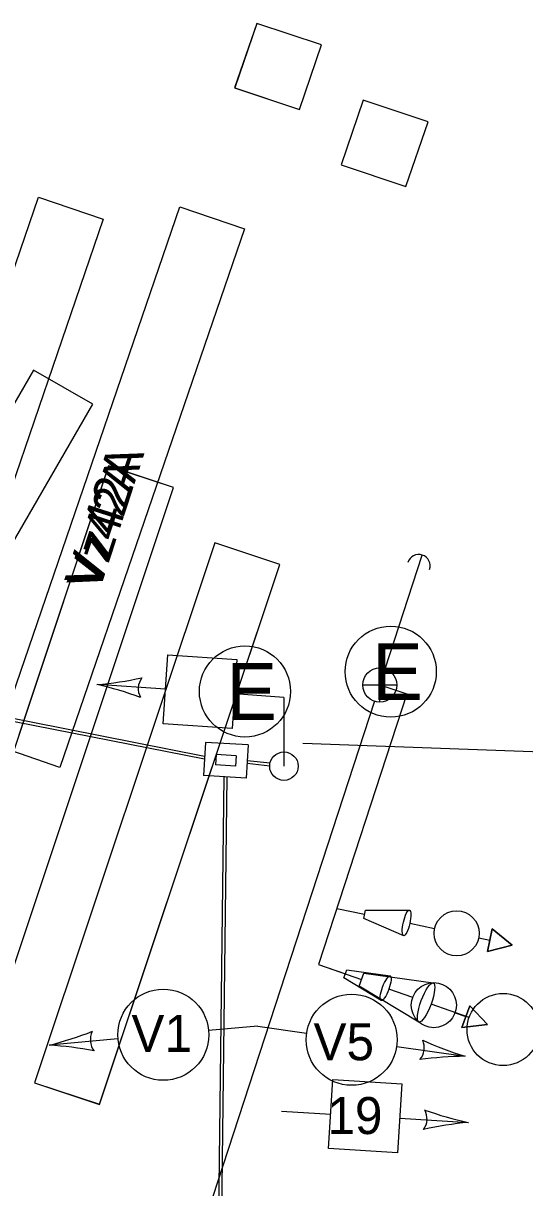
# Model space of a CAD drawing. Extents: x 647787 to 668496, y 640478 to 654412.
# Drawn here: x 661870.2 to 661914.2, y 647344.9 to 647447.2 of the extents above; entities that cross this region are included whole.
import ezdxf

# ---------------------------------------------------------------- set-up
doc = ezdxf.new("R2010")
doc.units = 0
for name, color, linetype in [('TEMP_DETECTION ZONE_STAGE 3', 7, 'Continuous'), ('TEMP_DETECTION_ZONE_STAGE 5', 7, 'Continuous'), ('TEMP_SIGNAL_HEAD_PED STAGES 1C', 7, 'Continuous'), ('TEMP_SIGNAL_HEAD_STAGE 1A', 7, 'Continuous'), ('TEMP_SIGNAL_HEAD_STAGE 2', 7, 'Continuous'), ('TEMP_SIGNAL_HEAD_STAGE 3 SHILO', 7, 'Continuous'), ('TEMP_SIGNAL_POLES_STAGE 1A', 7, 'Continuous'), ('TEMP_SIGNAL_POLES_STAGE 1B', 7, 'Continuous'), ('TEMP_SIGNAL_POLES_STAGE 2', 7, 'Continuous'), ('TEMP_SIGNAL_POLES_STAGE 3-1', 7, 'Continuous'), ('TEMP_SIGNAL_POLES_STAGE 5', 7, 'Continuous'), ('TEMP_SIGNAL_POLES_STAGES 3-4', 7, 'Continuous'), ('TEXT_TEMP_SIGNAL_POLES_STAGE 2', 7, 'Continuous'), ('TEXT_TEMP_SIGNAL_POLES_STAGE 3', 7, 'Continuous'), ('TEXT_TEMP_SIGNAL_POLES_STAGE 4', 7, 'Continuous'), ('TEXT_TEMP_SIGNAL_POLES_STAGE 5', 7, 'Continuous')]:
    doc.layers.add(name, color=color, linetype=linetype)

msp = doc.modelspace()

# ---------------------------------------------------------------- linework, layer by layer
at = {"layer": 'TEMP_DETECTION ZONE_STAGE 3'}
for points in [[(661890.66, 647447.21), (661888.71, 647441.54), (661894.41, 647439.64), (661896.35, 647445.31)], [(661890.66, 647447.21), (661888.71, 647441.54), (661894.41, 647439.64), (661896.35, 647445.31)], [(661890.66, 647447.21), (661888.71, 647441.54), (661894.41, 647439.64), (661896.35, 647445.31)], [(661890.66, 647447.21), (661888.72, 647441.54), (661894.41, 647439.64), (661896.35, 647445.31)], [(661900.01, 647440.47), (661898.06, 647434.79), (661903.75, 647432.89), (661905.7, 647438.57)], [(661900.01, 647440.47), (661898.06, 647434.79), (661903.75, 647432.89), (661905.7, 647438.57)], [(661900.01, 647440.47), (661898.06, 647434.79), (661903.75, 647432.89), (661905.7, 647438.57)], [(661900.01, 647440.47), (661898.06, 647434.79), (661903.75, 647432.89), (661905.7, 647438.57)], [(661846.03, 647373.46), (661851.22, 647370.46), (661876.25, 647413.75), (661871.05, 647416.75)], [(661846.03, 647373.46), (661851.22, 647370.46), (661876.25, 647413.75), (661871.05, 647416.75)], [(661846.03, 647373.46), (661851.22, 647370.46), (661876.25, 647413.75), (661871.05, 647416.75)], [(661846.03, 647373.47), (661851.22, 647370.46), (661876.25, 647413.75), (661871.06, 647416.75)], [(661861.82, 647360.91), (661867.51, 647359.01), (661883.34, 647406.44), (661877.65, 647408.34)], [(661861.82, 647360.91), (661867.51, 647359.01), (661883.34, 647406.43), (661877.64, 647408.33)], [(661861.82, 647360.91), (661867.51, 647359.01), (661883.34, 647406.43), (661877.64, 647408.33)], [(661861.82, 647360.91), (661867.51, 647359.01), (661883.34, 647406.43), (661877.64, 647408.33)], [(661871.15, 647354.16), (661876.84, 647352.26), (661892.67, 647399.69), (661886.98, 647401.59)], [(661871.15, 647354.16), (661876.84, 647352.26), (661892.67, 647399.69), (661886.98, 647401.59)], [(661871.15, 647354.16), (661876.84, 647352.26), (661892.67, 647399.69), (661886.98, 647401.59)], [(661871.15, 647354.17), (661876.85, 647352.27), (661892.67, 647399.69), (661886.98, 647401.59)]]:
    msp.add_lwpolyline(points, close=True, dxfattribs=at)
at = {"layer": 'TEMP_DETECTION_ZONE_STAGE 5'}
for points in [[(661860.97, 647382.71), (661855.29, 647384.65), (661871.5, 647431.95), (661877.18, 647430.01)], [(661873.37, 647381.86), (661867.69, 647383.8), (661883.89, 647431.1), (661889.57, 647429.16)]]:
    msp.add_lwpolyline(points, close=True, dxfattribs=at)
at = {"layer": 'TEMP_SIGNAL_HEAD_PED STAGES 1C'}
for points in [[(661897.68, 647369.47), (661900.13, 647368.96)], [(661897.68, 647369.47), (661900.13, 647368.96)], [(661900.05, 647368.59), (661900.21, 647369.32)], [(661900.05, 647368.59), (661900.21, 647369.32)], [(661900.21, 647369.32), (661904.06, 647369.32)], [(661900.21, 647369.32), (661904.06, 647369.32)], [(661903.57, 647367.08), (661900.05, 647368.59)], [(661903.57, 647367.08), (661900.05, 647368.59)], [(661906.27, 647367.69), (661904.09, 647368.14)], [(661906.27, 647367.69), (661904.09, 647368.14)], [(661910.91, 647365.69), (661911.34, 647367.67), (661913.09, 647366.25), (661910.91, 647365.69)], [(661910.91, 647365.69), (661911.34, 647367.67), (661913.09, 647366.25), (661910.91, 647365.69)], [(661910.15, 647366.89), (661911.12, 647366.68)], [(661910.15, 647366.89), (661911.12, 647366.68)], [(661896.08, 647364.56), (661898.44, 647363.73)], [(661896.08, 647364.56), (661898.44, 647363.73)], [(661898.31, 647363.37), (661898.56, 647364.07)], [(661898.31, 647363.37), (661898.56, 647364.07)], [(661898.56, 647364.07), (661902.38, 647363.55)], [(661898.56, 647364.07), (661902.38, 647363.55)], [(661901.59, 647361.39), (661898.31, 647363.37)], [(661901.59, 647361.39), (661898.31, 647363.37)], [(661904.35, 647361.64), (661902.25, 647362.38)], [(661904.35, 647361.64), (661902.25, 647362.38)], [(661908.67, 647359.03), (661909.37, 647360.93), (661910.91, 647359.29), (661908.67, 647359.03)], [(661908.67, 647359.03), (661909.37, 647360.93), (661910.91, 647359.29), (661908.67, 647359.03)], [(661908.08, 647360.32), (661909.02, 647359.98)], [(661908.08, 647360.32), (661909.02, 647359.98)]]:
    msp.add_lwpolyline(points, dxfattribs=at)
for points in [[(661913.09, 647366.25), (661911.34, 647367.67), (661910.91, 647365.69)], [(661913.09, 647366.25), (661911.34, 647367.67), (661910.91, 647365.69)], [(661910.91, 647359.29), (661909.37, 647360.93), (661908.67, 647359.03)], [(661910.91, 647359.29), (661909.37, 647360.93), (661908.67, 647359.03)]]:
    msp.add_lwpolyline(points, close=True, dxfattribs=at)
for centre in [(661908.21, 647367.29), (661908.21, 647367.29), (661906.21, 647360.98), (661906.21, 647360.98)]:
    msp.add_circle(centre, 1.98, dxfattribs=at)
for centre, major_axis in [((661903.81, 647368.2), (0.25, 1.12)), ((661903.81, 647368.2), (0.25, 1.12)), ((661901.98, 647362.47), (0.4, 1.08)), ((661901.98, 647362.47), (0.4, 1.08))]:
    msp.add_ellipse(centre, major_axis=major_axis, ratio=0.249111, dxfattribs=at)
at = {"layer": 'TEMP_SIGNAL_HEAD_STAGE 1A'}
for p, q in [((661848.93, 647390.18), (661886.08, 647382.86)), ((661848.93, 647390.18), (661886.08, 647382.86)), ((661848.93, 647389.92), (661886.07, 647382.61)), ((661848.93, 647389.92), (661886.07, 647382.61)), ((661886.15, 647384.06), (661885.98, 647381.15)), ((661886.15, 647384.06), (661885.98, 647381.15)), ((661889.9, 647383.83), (661886.15, 647384.06)), ((661889.9, 647383.83), (661886.15, 647384.06)), ((661889.9, 647383.83), (661889.72, 647380.92)), ((661889.9, 647383.83), (661889.72, 647380.92)), ((661887.09, 647383), (661887.04, 647382.08)), ((661887.09, 647383), (661887.04, 647382.08)), ((661888.84, 647382.89), (661887.09, 647383)), ((661888.84, 647382.89), (661887.09, 647383)), ((661888.84, 647382.89), (661888.78, 647381.98)), ((661888.84, 647382.89), (661888.78, 647381.98)), ((661891.82, 647382.23), (661889.81, 647382.45)), ((661891.82, 647382.23), (661889.81, 647382.45)), ((661888.78, 647381.98), (661887.04, 647382.08)), ((661888.78, 647381.98), (661887.04, 647382.08)), ((661891.79, 647381.98), (661889.8, 647382.2)), ((661891.79, 647381.98), (661889.8, 647382.2)), ((661889.72, 647380.92), (661885.98, 647381.15)), ((661889.72, 647380.92), (661885.98, 647381.15)), ((661887.77, 647381.04), (661886.27, 647256.08)), ((661887.77, 647381.04), (661886.27, 647256.08)), ((661888.02, 647381.02), (661886.52, 647256.07)), ((661888.02, 647381.02), (661886.52, 647256.07))]:
    msp.add_line(p, q, dxfattribs=at)
at = {"layer": 'TEMP_SIGNAL_HEAD_STAGE 2'}
for p, q in [((661890.75, 647359.13), (661886.43, 647358.74)), ((661890.75, 647359.13), (661895.03, 647358.51)), ((661878.47, 647358.02), (661872.43, 647357.47)), ((661902.95, 647357.36), (661908.95, 647356.49)), ((661892.82, 647351.67), (661897.16, 647351.41)), ((661903.21, 647351.05), (661909.24, 647350.68))]:
    msp.add_line(p, q, dxfattribs=at)
msp.add_lwpolyline([(661896.97, 647348.38), (661897.34, 647354.44), (661903.39, 647354.07), (661903.02, 647348.02)], close=True, dxfattribs=at)
for centre in [(661882.45, 647358.38), (661898.99, 647357.94)]:
    msp.add_circle(centre, 4, dxfattribs=at)
for centre, radius, start, end in [((661865.39, 647386.09), 29.47, 283.8189, 291.557), ((661877.67, 647357.94), 1.63, 153.3523, 217.0469), ((661903.74, 647357.25), 1.63, 319.9026, 23.5972), ((661917.49, 647384.7), 29.47, 245.4136, 253.1517), ((661870.68, 647328.05), 29.47, 78.8632, 86.6013), ((661909.14, 647327.02), 29.47, 90.3692, 98.1074), ((661903.98, 647351), 1.63, 324.7005, 28.3952), ((661915.39, 647379.5), 29.47, 250.2014, 257.9395), ((661911.89, 647321.33), 29.47, 95.1562, 102.8943)]:
    msp.add_arc(centre, radius, start, end, dxfattribs=at)
at = {"layer": 'TEMP_SIGNAL_HEAD_STAGE 3 SHILO'}
for points in [[(661896.08, 647364.56), (661899.85, 647363.23)], [(661896.08, 647364.56), (661899.85, 647363.23)], [(661899.64, 647362.66), (661900.06, 647363.78)], [(661899.64, 647362.66), (661900.06, 647363.78)], [(661900.06, 647363.78), (661906.16, 647362.94)], [(661900.06, 647363.78), (661906.16, 647362.94)], [(661904.89, 647359.5), (661899.64, 647362.66)], [(661904.89, 647359.5), (661899.64, 647362.66)], [(661909.31, 647359.89), (661905.96, 647361.07)], [(661909.31, 647359.89), (661905.96, 647361.07)]]:
    msp.add_lwpolyline(points, dxfattribs=at)
msp.add_circle((661912.29, 647358.84), 3.17, dxfattribs=at)
msp.add_circle((661912.29, 647358.84), 3.17, dxfattribs=at)
msp.add_ellipse((661905.53, 647361.22), major_axis=(0.63, 1.72), ratio=0.249111, dxfattribs=at)
msp.add_ellipse((661905.53, 647361.22), major_axis=(0.63, 1.72), ratio=0.249111, dxfattribs=at)
at = {"layer": 'TEMP_SIGNAL_POLES_STAGE 1A'}
for p, q in [((661882.65, 647388.72), (661876.63, 647389.14)), ((661893.04, 647388.01), (661888.7, 647388.31)), ((661893.04, 647388.01), (661893.04, 647381.97))]:
    msp.add_line(p, q, dxfattribs=at)
msp.add_lwpolyline([(661888.91, 647391.34), (661888.5, 647385.29), (661882.45, 647385.7), (661882.86, 647391.75)], close=True, dxfattribs=at)
msp.add_circle((661893.04, 647381.97), 1.25, dxfattribs=at)
for centre, radius, start, end in [((661874.21, 647418.51), 29.47, 274.7, 282.4381), ((661881.88, 647388.78), 1.63, 144.2443, 207.939), ((661870.24, 647360.36), 29.47, 69.7452, 77.4833)]:
    msp.add_arc(centre, radius, start, end, dxfattribs=at)
at = {"layer": 'TEMP_SIGNAL_POLES_STAGE 1B'}
for points in [[(661860.97, 647382.71), (661855.29, 647384.65), (661871.5, 647431.95), (661877.18, 647430.01)], [(661873.37, 647381.86), (661867.69, 647383.8), (661883.89, 647431.1), (661889.57, 647429.16)]]:
    msp.add_lwpolyline(points, close=True, dxfattribs=at)
at = {"layer": 'TEMP_SIGNAL_POLES_STAGE 2'}
msp.add_line((662012.45, 647379.68), (661894.7, 647383.95), dxfattribs=at)
at = {"layer": 'TEMP_SIGNAL_POLES_STAGE 3-1'}
msp.add_line((661901.46, 647389.1), (661903.84, 647388.32), dxfattribs=at)
msp.add_line((661901.46, 647389.1), (661903.84, 647388.32), dxfattribs=at)
msp.add_lwpolyline([(661903.84, 647388.32), (661896.08, 647364.56)], dxfattribs=at)
msp.add_lwpolyline([(661903.84, 647388.32), (661896.08, 647364.56)], dxfattribs=at)
at = {"layer": 'TEMP_SIGNAL_POLES_STAGE 5'}
msp.add_circle((661893.04, 647381.97), 1.25, dxfattribs=at)
at = {"layer": 'TEMP_SIGNAL_POLES_STAGES 3-4'}
for p, q in [((661901.93, 647390.53), (661905.19, 647400.51)), ((661901.93, 647390.53), (661905.19, 647400.51)), ((661901.46, 647387.6), (661901.46, 647390.6)), ((661901.46, 647387.6), (661901.46, 647390.6)), ((661899.96, 647389.1), (661902.96, 647389.1)), ((661899.96, 647389.1), (661902.96, 647389.1)), ((661901, 647387.67), (661859.96, 647262)), ((661901, 647387.67), (661859.96, 647262))]:
    msp.add_line(p, q, dxfattribs=at)
msp.add_circle((661901.46, 647389.1), 1.5, dxfattribs=at)
msp.add_circle((661901.46, 647389.1), 1.5, dxfattribs=at)
msp.add_arc((661904.88, 647399.56), 1, 341.9152, 161.9152, dxfattribs=at)
msp.add_arc((661904.88, 647399.56), 1, 341.9152, 161.9152, dxfattribs=at)
at = {"layer": 'TEXT_TEMP_SIGNAL_POLES_STAGE 2'}
msp.add_circle((661889.62, 647388.53), 4, dxfattribs=at)
at = {"layer": 'TEXT_TEMP_SIGNAL_POLES_STAGE 3'}
msp.add_circle((661889.62, 647388.53), 4, dxfattribs=at)
at = {"layer": 'TEXT_TEMP_SIGNAL_POLES_STAGE 4'}
msp.add_circle((661889.62, 647388.53), 4, dxfattribs=at)
at = {"layer": 'TEXT_TEMP_SIGNAL_POLES_STAGE 5'}
msp.add_circle((661902.42, 647390.27), 4, dxfattribs=at)

# ---------------------------------------------------------------- texts
at = {"layer": 'TEMP_DETECTION_ZONE_STAGE 5'}
msp.add_text('Vz42A', height=3, rotation=71.9202, dxfattribs=at).set_placement((661876.79, 647397.15))
at = {"layer": 'TEMP_SIGNAL_POLES_STAGE 1B'}
msp.add_text('Vz42A', height=3.25, rotation=71.9202, dxfattribs=at).set_placement((661876.83, 647397.29))
at = {"layer": 'TEXT_TEMP_SIGNAL_POLES_STAGE 2'}
for s, height, p in [('E', 5, (661887.98, 647386.03)), ('V1', 3.25, (661879.65, 647356.88)), ('V5', 3.25, (661895.64, 647356.14)), ('19', 3.25, (661896.86, 647349.66))]:
    msp.add_text(s, height=height, dxfattribs=at).set_placement(p)
at = {"layer": 'TEXT_TEMP_SIGNAL_POLES_STAGE 3'}
msp.add_text('E', height=5, dxfattribs=at).set_placement((661887.98, 647386.03))
at = {"layer": 'TEXT_TEMP_SIGNAL_POLES_STAGE 4'}
msp.add_text('E', height=5, dxfattribs=at).set_placement((661887.98, 647386.03))
at = {"layer": 'TEXT_TEMP_SIGNAL_POLES_STAGE 5'}
msp.add_text('E', height=5, dxfattribs=at).set_placement((661900.79, 647387.77))

doc.saveas('drawing.dxf')
